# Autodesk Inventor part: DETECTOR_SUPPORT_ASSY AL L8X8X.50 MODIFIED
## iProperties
Shininess: 64.0
Length Units: 11272
Angle Units: 11279
Time Units: 11290
Mass Units: 11286
Length Display Precision: 3
Angle Display Precision: 2
Compacted: True
Part Number: DETECTOR_SUPPORT_ASSY AL L8X8X.50 MODIFIED
Document SubType Name: Modeling
Created: 2004-08
Designer: John Blackburn
Material: ALUMINUM
Manufacturer: Standard
Standards Organization: Custom
Density: 0.0
Volumn: 0.0
Area: 0.0
PropertySet Name: Model Information
Control State: 0
Master: False
Checked Out: False
Author: John Blackburn
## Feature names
1. BaseExt [Extrusion]
2. Hole1
3. Hole2
4. Hole3
5. Hole4
6. Hole5
7. Hole6
